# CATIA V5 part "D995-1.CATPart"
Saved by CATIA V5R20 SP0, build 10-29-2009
Part number: D995-1
Source: Unknown
Property "ARTICLENO": "D995-1"
Property "BOMINFO": "D995-1"
Property "CODE": "D995-1"
Property "F1": "50.000"
Property "F2": "68.000"
Property "L": "240.000"
Property "L1": "182.000"
Property "L2": "118.000"
Property "L3": "115.000"
Property "LINA": "D995-1"
Property "NB": "D995-1"
Property "NBSYN": "$CODE."
Property "NN": "D995"
Property "NT": "D995"
Property "S": "50.000"
Property "SUPPLIER": "CF"
Bounding box of the stored display mesh (mm): x -22.5 to 22.5, y -257 to 0, z -22.5 to 22.5
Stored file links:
  C:\Users\Utente\Desktop\3D files D995\D995-1.CATPart
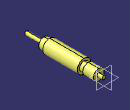
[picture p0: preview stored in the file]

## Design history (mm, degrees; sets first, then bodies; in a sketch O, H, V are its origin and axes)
Body1 "Geometry.1" (main body)
  Solid1 "D995-1.catpart": solid without history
